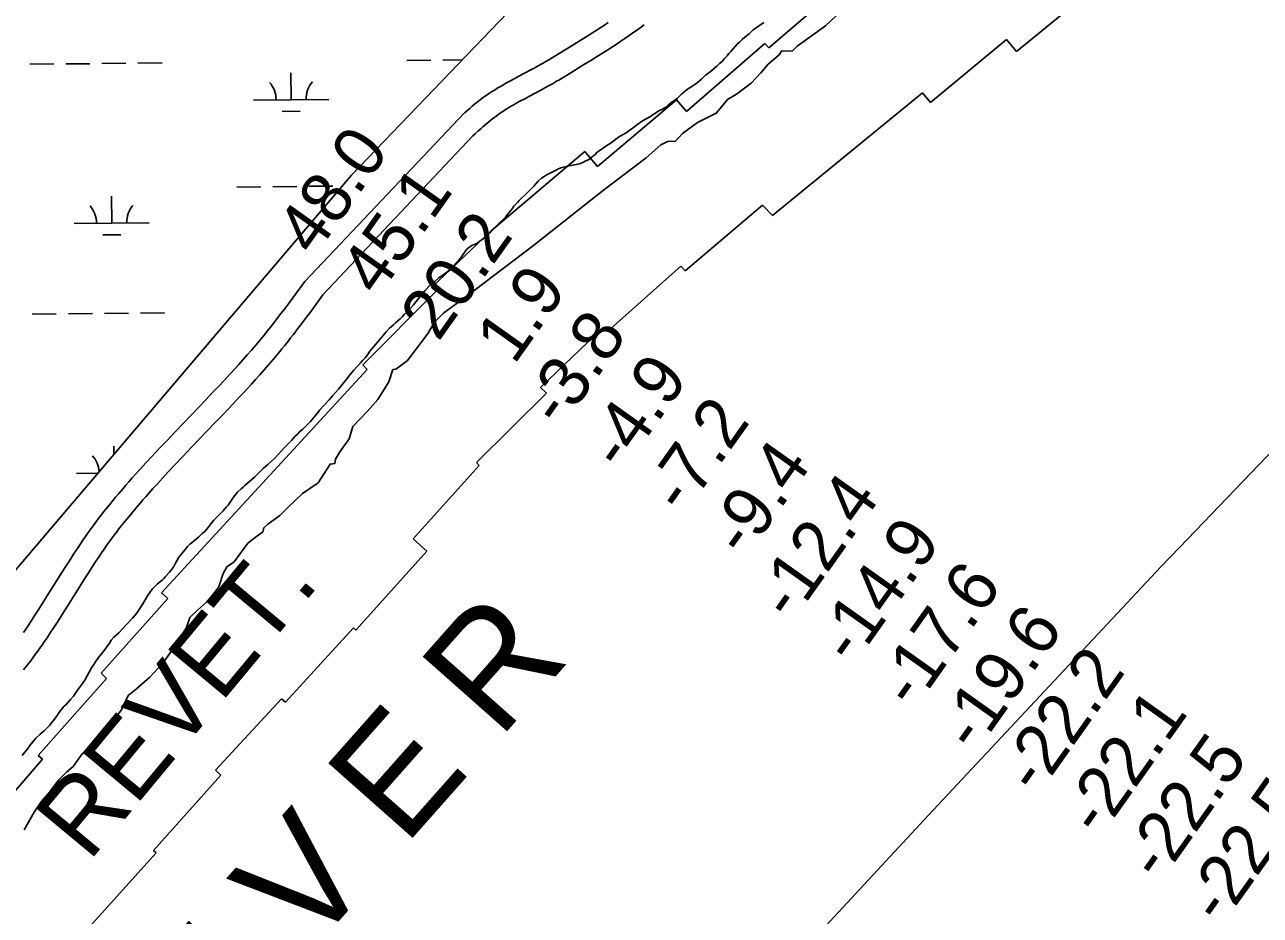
# Model space of a CAD drawing. Extents: x 3146026 to 3183936, y 897894 to 923344.
# Drawn here: x 3151306 to 3152950, y 918770 to 919955 of the extents above; entities that cross this region are included whole.
import ezdxf

# ---------------------------------------------------------------- set-up
doc = ezdxf.new("R2010")
doc.units = 0
for name, color, linetype in [('V-RIVR-EDGE', 7, 'Continuous'), ('V-RIVR-IDEN', 7, 'Continuous'), ('V-RIVR-RANG', 7, 'Continuous'), ('V-ROAD-CNTR', 7, 'Continuous'), ('V-RRAP-RVMT', 7, 'Continuous'), ('V-RRAP-RVMT-IDEN', 7, 'Continuous'), ('V-SITE-VEGE', 7, 'Continuous'), ('V-TOPO-BNDY', 7, 'Continuous'), ('V-WETL-SWMP', 7, 'Continuous')]:
    doc.layers.add(name, color=color, linetype=linetype)

msp = doc.modelspace()

# ---------------------------------------------------------------- linework, layer by layer
at = {"layer": 'V-RIVR-EDGE'}
for points in [[(3152392.8, 919973.7), (3152371.5, 919953.8), (3152333.9, 919927), (3152327, 919920.1), (3152313.3, 919920.8), (3152310.1, 919915.2), (3152295.1, 919902.7), (3152285.7, 919891.5), (3152272.5, 919877.7), (3152253.1, 919862.8), (3152241.2, 919855.9), (3152233.7, 919846.6), (3152226.2, 919837.8), (3152201.2, 919825.4), (3152181.1, 919810.5), (3152171.7, 919800.5), (3152161.1, 919799.9), (3152152.3, 919795.5), (3152132.9, 919778.1), (3152075.9, 919735.1), (3151981.3, 919660.3), (3151893, 919593), (3151863.6, 919571.8), (3151851.1, 919559.3), (3151842.9, 919545), (3151827.8, 919525), (3151814.7, 919508.2), (3151799.6, 919497), (3151795.9, 919496.3), (3151790.2, 919480.1), (3151775.8, 919456.4), (3151762, 919440.8), (3151742.3, 919420.8), (3151737.5, 919404), (3151725.3, 919387.1), (3151719.3, 919377.1), (3151718.7, 919371.5), (3151712.1, 919370.6), (3151696.1, 919345.6), (3151675.5, 919331.6), (3151656, 919312.9), (3151645.1, 919302), (3151629.1, 919290.5), (3151624.1, 919285.8), (3151622.8, 919280.2), (3151609.1, 919270.2), (3151602.8, 919265.2), (3151584.3, 919240.3), (3151574.9, 919233.7), (3151569.9, 919225), (3151563.9, 919207.2), (3151558.9, 919200), (3151547.9, 919186.9)], [(3151547.9, 919186.9), (3151535.7, 919176), (3151525.7, 919166.3), (3151520.9, 919152.9), (3151505.2, 919127.3), (3151489.6, 919105.5), (3151472.3, 919086.8), (3151454.5, 919071.5), (3151443.5, 919062.4), (3151434.4, 919043.7), (3151425.6, 919032.2), (3151420.6, 919024.1), (3151409.3, 919009.1), (3151395.8, 918995.1), (3151382.4, 918984.8), (3151370.4, 918968.2), (3151361.4, 918960.4), (3151351.3, 918950.2), (3151338.8, 918933.9), (3151327.8, 918921.1), (3151318.1, 918907.1), (3151305.2, 918883.7)]]:
    msp.add_lwpolyline(points, dxfattribs=at)
at = {"layer": 'V-ROAD-CNTR'}
for points in [[(3152082.5, 919958.2), (3152077.5, 919954.9), (3152072.8, 919951.9), (3152068.4, 919949), (3152064.3, 919946.4), (3152056.5, 919941.4), (3152049.6, 919937.1), (3152043.6, 919933.4), (3152033, 919926.9), (3152017, 919917.1), (3152000.9, 919907.4), (3151998.3, 919905.8), (3151995.7, 919904.3), (3151993.3, 919902.8), (3151988.4, 919900.1), (3151983.8, 919897.5), (3151979.4, 919895.1), (3151971, 919890.7), (3151963.6, 919886.8), (3151957.1, 919883.3), (3151951.3, 919880.2), (3151946.3, 919877.4), (3151941.9, 919874.9), (3151938, 919872.7), (3151934.7, 919870.7), (3151931.7, 919868.9), (3151929.2, 919867.3), (3151926.9, 919865.8), (3151923, 919863.3), (3151920.1, 919861.3), (3151917.9, 919859.7), (3151914.7, 919857.4), (3151911.5, 919855), (3151907.9, 919852.1), (3151904.5, 919849.4), (3151901.4, 919846.8), (3151898.5, 919844.3), (3151895.9, 919842), (3151893.4, 919839.8), (3151891.2, 919837.9)], [(3152130.1, 919955.3), (3152126.6, 919952.7), (3152123.1, 919950), (3152119.8, 919947.6), (3152116.6, 919945.3), (3152110.4, 919941), (3152104.6, 919937), (3152099.2, 919933.3), (3152094.1, 919929.9), (3152089.2, 919926.7), (3152084.7, 919923.8), (3152080.4, 919921.1), (3152072.5, 919916), (3152065.5, 919911.6), (3152059.3, 919907.8), (3152048.6, 919901.3), (3152032.6, 919891.5), (3152016.5, 919881.7), (3152013.7, 919880), (3152010.9, 919878.4), (3152008.2, 919876.8), (3152003, 919873.9), (3151998.1, 919871.2), (3151993.5, 919868.7), (3151985, 919864.2), (3151977.6, 919860.3), (3151971.2, 919856.9), (3151965.7, 919853.9), (3151960.9, 919851.2), (3151956.8, 919848.9), (3151953.3, 919846.8), (3151950.2, 919845), (3151947.5, 919843.4), (3151945.2, 919841.9), (3151943.3, 919840.7), (3151939.8, 919838.4), (3151937.3, 919836.6), (3151935.4, 919835.3), (3151932.6, 919833.3), (3151929.9, 919831.2), (3151926.6, 919828.6), (3151923.6, 919826.2), (3151920.7, 919823.8), (3151918.1, 919821.6), (3151915.6, 919819.4), (3151913.3, 919817.4), (3151909, 919813.5), (3151905.3, 919810.1), (3151902.2, 919807.3)], [(3151891.2, 919837.9), (3151678.6, 919613.7), (3151662.6, 919592), (3151656.7, 919584), (3151651.4, 919576.9), (3151646.8, 919570.8), (3151642.7, 919565.5)], [(3151902.2, 919807.3), (3151702.7, 919595.9), (3151686.8, 919574.2), (3151680.7, 919566), (3151675.4, 919558.9), (3151670.7, 919552.7), (3151666.6, 919547.3)], [(3151642.8, 919565.5), (3151639.2, 919560.9), (3151636.1, 919556.9), (3151633.3, 919553.4), (3151628.5, 919547.3), (3151624.8, 919542.7), (3151622.1, 919539.4), (3151617.9, 919534.3), (3151613.7, 919529.3), (3151607.7, 919522.4), (3151601.9, 919515.8), (3151596.2, 919509.4), (3151590.7, 919503.2), (3151585.2, 919497.2), (3151580, 919491.4), (3151574.8, 919485.8), (3151569.8, 919480.4), (3151564.9, 919475.2), (3151555.4, 919465.2), (3151546.5, 919455.7), (3151538, 919446.9), (3151506.2, 919413.8), (3151494.3, 919401.3), (3151483.9, 919390.3), (3151474.8, 919380.6), (3151466.9, 919372.1), (3151460.1, 919364.6), (3151454.1, 919358), (3151448.9, 919352.1), (3151444.4, 919347), (3151440.4, 919342.5), (3151437, 919338.6), (3151431, 919331.6), (3151426.6, 919326.4), (3151423.3, 919322.4), (3151418.4, 919316.4), (3151413.5, 919310.4), (3151411.1, 919307.4), (3151408.8, 919304.5), (3151406.6, 919301.6), (3151404.4, 919298.8), (3151402.2, 919295.9), (3151398.1, 919290.3), (3151394.1, 919284.9), (3151390.3, 919279.6), (3151386.7, 919274.4), (3151383.3, 919269.3), (3151379.9, 919264.5), (3151376.8, 919259.7), (3151373.7, 919255.1), (3151370.8, 919250.6), (3151365.2, 919241.9), (3151359.9, 919233.7), (3151355.1, 919226.1), (3151337.1, 919197.4), (3151330.4, 919186.7), (3151324.5, 919177.4), (3151319.3, 919169.4), (3151314.7, 919162.4), (3151310.6, 919156.3), (3151307, 919151), (3151303.9, 919146.4)], [(3151666.5, 919547.2), (3151662.9, 919542.5), (3151659.7, 919538.4), (3151656.9, 919534.8), (3151651.9, 919528.5), (3151648.1, 919523.8), (3151645.2, 919520.3), (3151640.9, 919515.1), (3151636.5, 919509.9), (3151630.4, 919502.8), (3151624.4, 919496), (3151618.6, 919489.4), (3151612.9, 919483.1), (3151607.4, 919477), (3151602.1, 919471.1), (3151596.8, 919465.4), (3151591.7, 919460), (3151586.8, 919454.7), (3151577.2, 919444.5), (3151568.2, 919435), (3151559.7, 919426.2), (3151527.9, 919393), (3151516, 919380.6), (3151505.7, 919369.7), (3151496.8, 919360.2), (3151489, 919351.8), (3151482.3, 919344.4), (3151476.4, 919337.9), (3151471.3, 919332.2), (3151466.9, 919327.2), (3151463.1, 919322.8), (3151459.7, 919319), (3151453.9, 919312.2), (3151449.6, 919307.1), (3151446.4, 919303.2), (3151441.6, 919297.4), (3151436.9, 919291.6), (3151434.6, 919288.8), (3151432.5, 919286), (3151430.3, 919283.3), (3151428.2, 919280.6), (3151426.2, 919277.9), (3151422.3, 919272.6), (3151418.5, 919267.4), (3151414.8, 919262.3), (3151411.4, 919257.3), (3151408, 919252.4), (3151404.8, 919247.7), (3151401.7, 919243.1), (3151398.8, 919238.6), (3151395.9, 919234.2), (3151390.4, 919225.7), (3151385.3, 919217.7), (3151380.5, 919210.1), (3151362.5, 919181.4), (3151355.7, 919170.6), (3151349.7, 919161.2), (3151344.4, 919153), (3151339.7, 919145.8), (3151335.5, 919139.5), (3151331.8, 919134.1), (3151328.5, 919129.3), (3151325.6, 919125.2), (3151323, 919121.6), (3151320.7, 919118.4), (3151316.7, 919112.9), (3151313.7, 919108.8), (3151311.3, 919105.7), (3151307.8, 919101.2), (3151304.3, 919096.7)]]:
    msp.add_lwpolyline(points, dxfattribs=at)
at = {"layer": 'V-RRAP-RVMT'}
for p, q in [((3152296, 919924.5), (3152386.9, 920002.4)), ((3152726.7, 920002.2), (3152625.7, 919919.7)), ((3152186.7, 919840), (3152290.9, 919930.5)), ((3152290.9, 919930.5), (3152296, 919924.5)), ((3152612.6, 919935.8), (3152511.2, 919851.7)), ((3152625.7, 919919.7), (3152612.6, 919935.8)), ((3152500.5, 919864.6), (3152300.8, 919701.3)), ((3152511.2, 919851.7), (3152500.5, 919864.6)), ((3152068.3, 919766.7), (3152173.3, 919855.2)), ((3152173.3, 919855.2), (3152186.7, 919840)), ((3151926.6, 919681.2), (3152051.2, 919786.4)), ((3152051.2, 919786.4), (3152068.3, 919766.7)), ((3152287.5, 919715.2), (3152184.7, 919627.8)), ((3152300.8, 919701.3), (3152287.5, 919715.2)), ((3151847.1, 919605.5), (3151926.6, 919681.2)), ((3152179, 919633.8), (3152081.2, 919547.1)), ((3152184.7, 919627.8), (3152179, 919633.8)), ((3151755.6, 919502.6), (3151852.7, 919600.1)), ((3151852.7, 919600.1), (3151847.1, 919605.5)), ((3152076, 919552.7), (3151992.4, 919472.6)), ((3152081.2, 919547.1), (3152076, 919552.7)), ((3151488, 919199.2), (3151761.7, 919496.6)), ((3151761.7, 919496.6), (3151755.6, 919502.6)), ((3152000, 919464.9), (3151907.2, 919372.6)), ((3151992.4, 919472.6), (3152000, 919464.9)), ((3151910.7, 919368.7), (3151822.6, 919271.1)), ((3151907.2, 919372.6), (3151910.7, 919368.7)), ((3151822.6, 919271.1), (3151840.9, 919254.6)), ((3151840.9, 919254.6), (3151746.6, 919149.7)), ((3151407.7, 919092.3), (3151496.3, 919191.9)), ((3151496.3, 919191.9), (3151488, 919199.2)), ((3151743.2, 919152.8), (3151653, 919053.5)), ((3151746.6, 919149.7), (3151743.2, 919152.8)), ((3151323.6, 918982.6), (3151414.5, 919085.3)), ((3151414.5, 919085.3), (3151407.7, 919092.3)), ((3151647.5, 919058), (3151559.8, 918963)), ((3151653, 919053.5), (3151647.5, 919058)), ((3151242.7, 918877.6), (3151329.4, 918977.7)), ((3151329.4, 918977.7), (3151323.6, 918982.6)), ((3151566.8, 918956.5), (3151477, 918856.4)), ((3151559.8, 918963), (3151566.8, 918956.5)), ((3151477, 918856.4), (3151480.6, 918853.3)), ((3151480.6, 918853.3), (3151391.8, 918754.8))]:
    msp.add_line(p, q, dxfattribs=at)
at = {"layer": 'V-SITE-VEGE'}
for p, q in [((3152282.2, 919953.5), (3152289.7, 919958.4)), ((3152264, 919938.6), (3152269.8, 919943.3)), ((3152269.8, 919943.3), (3152275.1, 919948.4)), ((3152275.1, 919948.4), (3152282.2, 919953.5)), ((3152245.5, 919919.9), (3152253.8, 919929.6)), ((3152253.8, 919929.6), (3152257.4, 919932.6)), ((3152257.4, 919932.6), (3152260.6, 919935.7)), ((3152260.6, 919935.7), (3152264, 919938.6)), ((3152234.6, 919907), (3152237.3, 919910.4)), ((3152237.3, 919910.4), (3152240.7, 919914)), ((3152240.7, 919914), (3152242.8, 919917)), ((3152242.8, 919917), (3152245.5, 919919.9)), ((3152212, 919888.2), (3152218.1, 919892.8)), ((3152218.1, 919892.8), (3152226.8, 919900.1)), ((3152226.8, 919900.1), (3152230.5, 919903.6)), ((3152230.5, 919903.6), (3152234.6, 919907)), ((3152192.1, 919872.3), (3152195.5, 919874.3)), ((3152195.5, 919874.3), (3152198.9, 919876.5)), ((3152198.9, 919876.5), (3152201.4, 919878.4)), ((3152201.4, 919878.4), (3152206.5, 919882.8)), ((3152206.5, 919882.8), (3152212, 919888.2)), ((3152174.4, 919857.5), (3152180, 919862.8)), ((3152180, 919862.8), (3152185.3, 919867.5)), ((3152185.3, 919867.5), (3152189.2, 919870.4)), ((3152189.2, 919870.4), (3152192.1, 919872.3)), ((3152150.6, 919841.1), (3152153.8, 919842.6)), ((3152153.8, 919842.6), (3152160.6, 919846.7)), ((3152160.6, 919846.7), (3152163.5, 919849.4)), ((3152163.5, 919849.4), (3152174.4, 919857.5)), ((3152120.3, 919822.3), (3152128, 919827.4)), ((3152128, 919827.4), (3152138.7, 919833.3)), ((3152138.7, 919833.3), (3152142.4, 919835.7)), ((3152142.4, 919835.7), (3152145.3, 919837.5)), ((3152145.3, 919837.5), (3152147.7, 919839.4)), ((3152147.7, 919839.4), (3152150.6, 919841.1)), ((3152096.2, 919805.5), (3152101.3, 919808.7)), ((3152101.3, 919808.7), (3152106.2, 919811.3)), ((3152106.2, 919811.3), (3152109.6, 919814)), ((3152109.6, 919814), (3152115.9, 919818.4)), ((3152115.9, 919818.4), (3152120.3, 919822.3)), ((3152070.3, 919787.4), (3152080.5, 919794.5)), ((3152080.5, 919794.5), (3152084.8, 919797.2)), ((3152084.8, 919797.2), (3152088.5, 919800.1)), ((3152088.5, 919800.1), (3152096.2, 919805.5)), ((3152053.3, 919774.5), (3152056.2, 919775.7)), ((3152056.2, 919775.7), (3152064.9, 919782.6)), ((3152064.9, 919782.6), (3152067.8, 919785.5)), ((3152067.8, 919785.5), (3152070.3, 919787.4)), ((3152005.2, 919757.9), (3152012.2, 919761.3)), ((3152012.2, 919761.3), (3152015.1, 919763)), ((3152015.1, 919763), (3152019.5, 919764.9)), ((3152019.5, 919764.9), (3152028, 919767.2)), ((3152028, 919767.2), (3152044.3, 919770.4)), ((3152044.3, 919770.4), (3152047.7, 919771.6)), ((3152047.7, 919771.6), (3152053.3, 919774.5)), ((3151983.3, 919740.5), (3151989.1, 919747.1)), ((3151989.1, 919747.1), (3151993.5, 919751.3)), ((3151993.5, 919751.3), (3152002.2, 919756.6)), ((3152002.2, 919756.6), (3152005.2, 919757.9)), ((3151963.9, 919721.5), (3151974.8, 919732)), ((3151974.8, 919732), (3151983.3, 919740.5)), ((3151952.3, 919707.7), (3151954.4, 919710.1)), ((3151954.4, 919710.1), (3151956.9, 919713.7)), ((3151956.9, 919713.7), (3151961.5, 919718.6)), ((3151961.5, 919718.6), (3151963.9, 919721.5)), ((3151935, 919689.1), (3151945.5, 919699.1)), ((3151945.5, 919699.1), (3151950.3, 919705)), ((3151950.3, 919705), (3151952.3, 919707.7)), ((3151922.7, 919676.5), (3151926.1, 919679.6)), ((3151926.1, 919679.6), (3151929.9, 919684)), ((3151929.9, 919684), (3151935, 919689.1)), ((3151894.7, 919657.2), (3151901.3, 919661.8)), ((3151901.3, 919661.8), (3151904.2, 919662.8)), ((3151904.2, 919662.8), (3151907.9, 919664.8)), ((3151907.9, 919664.8), (3151912, 919667.7)), ((3151912, 919667.7), (3151914.4, 919669.6)), ((3151914.4, 919669.6), (3151917.6, 919671.6)), ((3151917.6, 919671.6), (3151920.2, 919673.8)), ((3151920.2, 919673.8), (3151922.7, 919676.5)), ((3151884.8, 919643.8), (3151887, 919646.5)), ((3151887, 919646.5), (3151892.8, 919654.7)), ((3151892.8, 919654.7), (3151894.7, 919657.2)), ((3151865.9, 919624.8), (3151872, 919629.7)), ((3151872, 919629.7), (3151884.8, 919643.8)), ((3151845.3, 919608.7), (3151851.8, 919613.8)), ((3151851.8, 919613.8), (3151857.1, 919618.4)), ((3151857.1, 919618.4), (3151865.9, 919624.8)), ((3151823.2, 919582.4), (3151833.4, 919595.3)), ((3151833.4, 919595.3), (3151838.2, 919601.1)), ((3151838.2, 919601.1), (3151845.3, 919608.7)), ((3151817.1, 919576), (3151819.8, 919578.5)), ((3151819.8, 919578.5), (3151823.2, 919582.4)), ((3151799.4, 919558.7), (3151805.5, 919563.8)), ((3151805.5, 919563.8), (3151808.1, 919566.5)), ((3151808.1, 919566.5), (3151810.6, 919569.5)), ((3151810.6, 919569.5), (3151814.7, 919573.4)), ((3151814.7, 919573.4), (3151817.1, 919576)), ((3151782.4, 919541.2), (3151787, 919546.8)), ((3151787, 919546.8), (3151790.9, 919550.9)), ((3151790.9, 919550.9), (3151797, 919556.3)), ((3151797, 919556.3), (3151799.4, 919558.7)), ((3151768.4, 919524.4), (3151780, 919538.7)), ((3151780, 919538.7), (3151782.4, 919541.2)), ((3151758.9, 919512.2), (3151761.8, 919515.8)), ((3151761.8, 919515.8), (3151765, 919520.7)), ((3151765, 919520.7), (3151768.4, 919524.4)), ((3151743.6, 919495.6), (3151753.3, 919505.9)), ((3151753.3, 919505.9), (3151755.8, 919509)), ((3151755.8, 919509), (3151758.9, 919512.2)), ((3151723.5, 919470.5), (3151734.7, 919484.4)), ((3151734.7, 919484.4), (3151736.6, 919487.1)), ((3151736.6, 919487.1), (3151743.6, 919495.6)), ((3151715.5, 919461.5), (3151723.5, 919470.5)), ((3151698, 919442.5), (3151704.1, 919449.1)), ((3151704.1, 919449.1), (3151711.1, 919456.2)), ((3151711.1, 919456.2), (3151715.5, 919461.5)), ((3151685.9, 919427.2), (3151696.1, 919439.6)), ((3151696.1, 919439.6), (3151698, 919442.5)), ((3151668.9, 919410.6), (3151671.8, 919413.8)), ((3151671.8, 919413.8), (3151676, 919416.9)), ((3151676, 919416.9), (3151685.9, 919427.2)), ((3151651.2, 919392.1), (3151660.9, 919401.8)), ((3151660.9, 919401.8), (3151663.1, 919404.7)), ((3151663.1, 919404.7), (3151665.3, 919407.2)), ((3151665.3, 919407.2), (3151668.9, 919410.6)), ((3151639.1, 919379.1), (3151651.2, 919392.1)), ((3151611.7, 919353.3), (3151623.1, 919364.5)), ((3151623.1, 919364.5), (3151629.1, 919369.9)), ((3151629.1, 919369.9), (3151639.1, 919379.1)), ((3151598.8, 919341.9), (3151611.7, 919353.3)), ((3151583.5, 919326.5), (3151589.1, 919333.3)), ((3151589.1, 919333.3), (3151594, 919337.7)), ((3151594, 919337.7), (3151596.6, 919339.7)), ((3151596.6, 919339.7), (3151598.8, 919341.9)), ((3151573.8, 919313.1), (3151576.3, 919316)), ((3151576.3, 919316), (3151583.5, 919326.5)), ((3151557.6, 919296), (3151569.7, 919308.5)), ((3151569.7, 919308.5), (3151573.8, 919313.1)), ((3151545, 919280.5), (3151550.1, 919286.3)), ((3151550.1, 919286.3), (3151552, 919289.5)), ((3151552, 919289.5), (3151557.6, 919296)), ((3151525.6, 919264.1), (3151529.2, 919266.6)), ((3151529.2, 919266.6), (3151531.6, 919269)), ((3151531.6, 919269), (3151537.5, 919273.6)), ((3151537.5, 919273.6), (3151542.1, 919278)), ((3151542.1, 919278), (3151545, 919280.5)), ((3151511, 919246.6), (3151515.1, 919251.9)), ((3151515.1, 919251.9), (3151517.6, 919254.6)), ((3151517.6, 919254.6), (3151522.2, 919260.7)), ((3151522.2, 919260.7), (3151525.6, 919264.1)), ((3151500.3, 919229), (3151504, 919234.4)), ((3151504, 919234.4), (3151506.2, 919238.5)), ((3151506.2, 919238.5), (3151511, 919246.6)), ((3151488.7, 919216.1), (3151490.9, 919218.3)), ((3151490.9, 919218.3), (3151493.1, 919221)), ((3151493.1, 919221), (3151498.4, 919226.6)), ((3151498.4, 919226.6), (3151500.3, 919229)), ((3151469.1, 919195.4), (3151475.4, 919204.2)), ((3151475.4, 919204.2), (3151482.4, 919211.2)), ((3151482.4, 919211.2), (3151488.7, 919216.1)), ((3151454.5, 919171.8), (3151463, 919184.7)), ((3151463, 919184.7), (3151469.1, 919195.4)), ((3151449.2, 919165.5), (3151454.5, 919171.8)), ((3151430.8, 919146.2), (3151441.4, 919156.9)), ((3151441.4, 919156.9), (3151449.2, 919165.5)), ((3151418.4, 919132.1), (3151421, 919136.2)), ((3151421, 919136.2), (3151424.4, 919140.4)), ((3151424.4, 919140.4), (3151430.8, 919146.2)), ((3151405.3, 919115), (3151410.1, 919120.9)), ((3151410.1, 919120.9), (3151418.4, 919132.1)), ((3151394.4, 919099.2), (3151396.8, 919102.4)), ((3151396.8, 919102.4), (3151400.9, 919108.7)), ((3151400.9, 919108.7), (3151405.3, 919115)), ((3151385.9, 919083.1), (3151394.4, 919099.2)), ((3151370.6, 919061.9), (3151376.2, 919069.5)), ((3151376.2, 919069.5), (3151381.1, 919077)), ((3151381.1, 919077), (3151385.9, 919083.1)), ((3151360.9, 919050.5), (3151366.8, 919057.1)), ((3151366.8, 919057.1), (3151370.6, 919061.9)), ((3151346.9, 919032.9), (3151351.5, 919040)), ((3151351.5, 919040), (3151353.4, 919042.7)), ((3151353.4, 919042.7), (3151358.3, 919048.3)), ((3151358.3, 919048.3), (3151360.9, 919050.5)), ((3151331.8, 919015.6), (3151336.7, 919020.5)), ((3151336.7, 919020.5), (3151339.1, 919023.2)), ((3151339.1, 919023.2), (3151341.5, 919026.4)), ((3151341.5, 919026.4), (3151343.7, 919028.8)), ((3151343.7, 919028.8), (3151346.9, 919032.9)), ((3151312.7, 918995.9), (3151320.4, 919005.6)), ((3151320.4, 919005.6), (3151326.3, 919011.3)), ((3151326.3, 919011.3), (3151329.2, 919013.7)), ((3151329.2, 919013.7), (3151331.8, 919015.6)), ((3151302.3, 918982.7), (3151310.5, 918992.7)), ((3151310.5, 918992.7), (3151312.7, 918995.9))]:
    msp.add_line(p, q, dxfattribs=at)
at = {"layer": 'V-TOPO-BNDY'}
msp.add_lwpolyline([(3151352.6, 917210), (3151351.8, 917287.8), (3151437.6, 917515.3), (3151454.3, 917560), (3151470.7, 917602.4), (3151731.9, 917952.4), (3152126.9, 918492), (3152508.8, 918903.5), (3152818, 919233.7), (3152842.7, 919259.6), (3153265.7, 919700), (3153697.1, 920260.1), (3153745.3, 920322.8), (3153843.6, 920396.5), (3154495.8, 920886), (3154603.3, 920966.4), (3154757.1, 921061.6), (3155165.9, 921315.5), (3155302.7, 921422.4), (3155461.9, 921546.6)], dxfattribs=at)
at = {"layer": 'V-WETL-SWMP'}
for p, q in [((3151814.4, 919907.8), (3151846.4, 919908.1)), ((3151862.4, 919908.2), (3151887.7, 919908.5)), ((3151312.5, 919902.8), (3151344.5, 919903.1)), ((3151360.5, 919903.2), (3151392.5, 919903.5)), ((3151408.5, 919903.7), (3151440.5, 919904)), ((3151456.5, 919904.2), (3151488.5, 919904.5)), ((3151660.3, 919855.5), (3151660, 919891.5)), ((3151610.3, 919855), (3151710.3, 919856)), ((3151648.5, 919839.9), (3151672.5, 919840.2)), ((3151421.5, 919691.2), (3151421.1, 919727.2)), ((3151588.1, 919739.3), (3151620.1, 919739.6)), ((3151636.1, 919739.8), (3151668.1, 919740.1)), ((3151684.1, 919740.3), (3151716, 919740.6)), ((3151371.5, 919690.7), (3151471.5, 919691.7)), ((3151409.6, 919675.7), (3151433.6, 919675.9)), ((3151315.8, 919570.1), (3151347.8, 919570.4)), ((3151363.8, 919570.6), (3151395.8, 919570.9)), ((3151411.8, 919571), (3151443.8, 919571.4)), ((3151459.8, 919571.5), (3151491.8, 919571.8)), ((3151424.5, 919384.1), (3151424.4, 919394.6)), ((3151374.8, 919358.1), (3151402.6, 919358.3))]:
    msp.add_line(p, q, dxfattribs=at)
msp.add_lwpolyline([(3154156.3, 921550.8), (3150311.9, 921563.1), (3150299.2, 918069.2), (3150852.3, 918711.7), (3151740.5, 919755.3), (3152243.5, 920278.8), (3152339.1, 920369.4), (3152421.5, 920426.9), (3152514.9, 920450.7), (3152616.2, 920465.1), (3152932.2, 920578.6), (3153209.3, 920814.1), (3153778.6, 921266.6), (3154156.3, 921550.8)], dxfattribs=at)
for centre, start, end in [((3151605.1, 919855.4), 359.7992, 41.3429), ((3151715.5, 919856.5), 139.7992, 181.3429), ((3151366.2, 919691.1), 359.7992, 41.3429), ((3151476.7, 919692.2), 139.7992, 181.3429), ((3151369.5, 919358.5), 3.719, 41.3429)]:
    msp.add_arc(centre, 35.2, start, end, dxfattribs=at)

# ---------------------------------------------------------------- texts
at = {"layer": 'V-RIVR-IDEN'}
msp.add_text('R I V E R', height=150, rotation=48.4686, dxfattribs=at).set_placement((3151478.6, 918485.3))
at = {"layer": 'V-RIVR-RANG'}
for s, p in [('48.0', (3151691.2, 919645.3)), ('45.1', (3151775.9, 919591.9)), ('20.2', (3151856.2, 919532.3)), ('1.9', (3151957, 919501.5)), ('-3.8', (3152019.5, 919416.9)), ('-4.9', (3152101.1, 919359)), ('-7.2', (3152182.9, 919301.5)), ('-9.4', (3152264.6, 919243.8)), ('-12.4', (3152327, 919159)), ('-14.9', (3152408.5, 919101.1)), ('-17.6', (3152489.3, 919042.1)), ('-19.6', (3152570.9, 918984.4)), ('-22.2', (3152653.7, 918928.2)), ('-22.1', (3152736.7, 918872.4)), ('-22.5', (3152817, 918812.7)), ('-22.5', (3152898.7, 918755))]:
    msp.add_text(s, height=67, rotation=54.6183, dxfattribs=at).set_placement(p)
at = {"layer": 'V-RRAP-RVMT-IDEN'}
msp.add_text('REVET.', height=100, rotation=50.2983, dxfattribs=at).set_placement((3151391, 918839.9))

doc.saveas('drawing.dxf')
